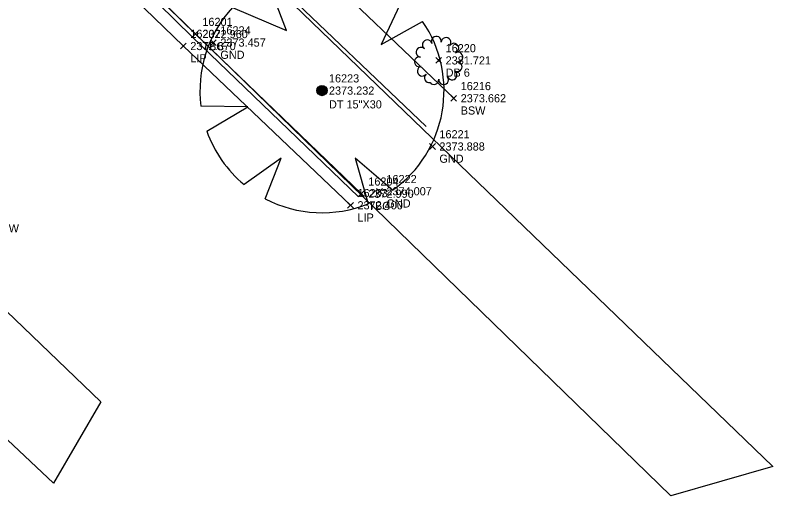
# Model space of a CAD drawing. Extents: x 2377639 to 2379738, y 729875 to 732734.
# Drawn here: x 2378181.6 to 2378274.7, y 730250.4 to 730309.5 of the extents above; entities that cross this region are included whole.
import ezdxf

# ---------------------------------------------------------------- set-up
doc = ezdxf.new("R2010")
doc.units = 0
for name, color, linetype in [('Default', 7, 'Continuous'), ('TOPO_CURBGTR_Back-of-Curb', 7, 'Continuous'), ('TOPO_CURBGTR_Face-of-Curb', 7, 'Continuous'), ('TOPO_CURBGTR_Lip-of-Gutter', 7, 'Continuous'), ('TOPO_DATA_Elevations', 7, 'Continuous'), ('TOPO_LNDSCP_Misc', 7, 'Continuous'), ('TOPO_LNDSCP_Tree', 7, 'Continuous'), ('TOPO_SW_Back', 7, 'Continuous')]:
    doc.layers.add(name, color=color, linetype=linetype)

# ---------------------------------------------------------------- blocks, each defined once
blk = doc.blocks.new('DB_2')
at = {"layer": 'Default'}
for centre, radius, start, end in [((-0.0121, 0.0998), 0.0254, 347.9823, 206.2388), ((0.0381, 0.0934), 0.0254, 319.1823, 177.4388), ((-0.0592, 0.0812), 0.0254, 16.7823, 235.0388), ((0.079, 0.0636), 0.0254, 290.3823, 148.6388), ((-0.0916, 0.0423), 0.0254, 45.5823, 263.8388), ((0.1005, 0.0177), 0.0254, 261.5823, 119.8388), ((-0.1011, -0.0074), 0.0254, 74.3823, 292.6388), ((0, 0), 0.00318, 0, 180), ((0, 0), 0.00318, 180, 0), ((-0.0856, -0.0556), 0.0254, 103.1823, 321.4388), ((0.0972, -0.0328), 0.0254, 232.7823, 91.0388), ((-0.0487, -0.0903), 0.0254, 131.9823, 278.4601), ((0.07, -0.0755), 0.0254, 203.9823, 62.2388), ((-0.025, -0.0997), 0.0254, 218.161, 4.6388), ((0.0256, -0.0998), 0.0254, 175.1823, 33.4388)]:
    blk.add_arc(centre, radius, start, end, dxfattribs=at)
blk = doc.blocks.new('DT_2')
at = {"layer": 'Default'}
for p, q in [((-0.03698, 0.06247), (-0.05646, 0.11375)), ((0.08381, 0.0954), (0.06151, 0.04792)), ((-0.09298, 0.0865), (-0.03698, 0.06247)), ((0.06151, 0.04792), (0.10461, 0.072)), ((-0.07727, -0.017), (-0.12593, -0.01636)), ((-0.11978, -0.04218), (-0.07727, -0.017)), ((-0.04258, -0.07017), (-0.0811, -0.09772)), ((-0.05897, -0.11247), (-0.04258, -0.07017)), ((0.07336, -0.10366), (0.03465, -0.07017)), ((0.03465, -0.07017), (0.04801, -0.11757))]:
    blk.add_line(p, q, dxfattribs=at)
for start, end in [(48.70125, 116.39792), (137.06823, 187.40379), (305.28646, 34.53794), (199.39852, 230.30841), (242.32871, 292.21141)]:
    blk.add_arc((0, 0), 0.12699, start, end, dxfattribs=at)
blk = doc.blocks.new('STUMP_4')
at = {"layer": 'Default'}
for q in [(-0.0106, 0.0008), (-0.0106, 0), (-0.0106, -0.0008), (-0.0105, 0.0017), (-0.0105, -0.0017), (-0.0103, 0.0025), (-0.0103, -0.0025), (-0.0101, 0.0033), (-0.0101, -0.0033), (-0.0098, 0.004), (-0.0098, -0.004), (-0.0094, 0.0048), (-0.0094, -0.0048), (-0.009, 0.0055), (-0.009, -0.0055), (-0.0086, 0.0062), (-0.0086, -0.0062), (-0.008, 0.0069), (-0.008, -0.0069), (-0.0075, 0.0075), (-0.0075, -0.0075), (-0.0069, 0.008), (-0.0069, -0.008), (-0.0062, 0.0086), (-0.0062, -0.0086), (-0.0055, 0.009), (-0.0055, -0.009), (-0.0048, 0.0094), (-0.0048, -0.0094), (-0.004, 0.0098), (-0.004, -0.0098), (-0.0033, 0.0101), (-0.0033, -0.0101), (-0.0025, 0.0103), (-0.0025, -0.0103), (-0.0017, 0.0105), (-0.0017, -0.0105), (-0.0008, 0.0106), (-0.0008, -0.0106), (0, 0.0106), (0.0008, 0.0106), (0.0017, 0.0105), (0.0025, 0.0103), (0.0033, 0.0101), (0.004, 0.0098), (0.0048, 0.0094), (0.0055, 0.009), (0.0062, 0.0086), (0.0069, 0.008), (0.0075, 0.0075), (0.008, 0.0069), (0.0086, 0.0062), (0.009, 0.0055), (0.0094, 0.0048), (0.0098, 0.004), (0.0101, 0.0033), (0.0103, 0.0025), (0.0105, 0.0017), (0.0106, 0.0008), (0.0062, -0.0086), (0.0069, -0.008), (0.0075, -0.0075), (0.008, -0.0069), (0.0086, -0.0062), (0.009, -0.0055), (0.004, -0.0098), (0.0048, -0.0094), (0.0055, -0.009), (0.0094, -0.0048), (0.0098, -0.004), (0.0101, -0.0033), (0.0103, -0.0025), (0.0105, -0.0017), (0.0106, -0.0008), (0.0106, 0), (0, -0.0106), (0.0008, -0.0106), (0.0017, -0.0105), (0.0025, -0.0103), (0.0033, -0.0101)]:
    blk.add_line((0, 0), q, dxfattribs=at)
blk.add_circle((0, 0), 0.0106, dxfattribs=at)

msp = doc.modelspace()

# ---------------------------------------------------------------- linework, layer by layer
at = {"layer": 'TOPO_CURBGTR_Back-of-Curb'}
msp.add_lwpolyline([(2378195.23, 730315.426), (2378203.719, 730307.132), (2378224.111, 730287.528)], dxfattribs=at)
at = {"layer": 'TOPO_CURBGTR_Face-of-Curb'}
msp.add_lwpolyline([(2378194.906, 730315.045), (2378203.371, 730306.773), (2378223.764, 730287.168)], dxfattribs=at)
at = {"layer": 'TOPO_CURBGTR_Lip-of-Gutter'}
msp.add_lwpolyline([(2378193.91, 730313.764), (2378202.238, 730305.665), (2378222.78, 730286.111)], dxfattribs=at)
at = {"layer": 'TOPO_DATA_Elevations'}
for p, q in [((2378203.365, 730306.778), (2378204.073, 730307.486)), ((2378203.365, 730307.486), (2378204.073, 730306.778)), ((2378203.365, 730306.778), (2378204.073, 730307.486)), ((2378203.365, 730307.486), (2378204.073, 730306.778)), ((2378201.884, 730305.311), (2378202.592, 730306.019)), ((2378201.884, 730306.019), (2378202.592, 730305.311)), ((2378201.884, 730305.311), (2378202.592, 730306.019)), ((2378201.884, 730306.019), (2378202.592, 730305.311)), ((2378205.575, 730305.738), (2378206.283, 730306.446)), ((2378205.575, 730306.446), (2378206.283, 730305.738)), ((2378205.575, 730305.738), (2378206.283, 730306.446)), ((2378205.575, 730306.446), (2378206.283, 730305.738)), ((2378233.258, 730303.544), (2378233.966, 730304.252)), ((2378233.258, 730304.252), (2378233.966, 730303.544)), ((2378233.258, 730303.544), (2378233.966, 730304.252)), ((2378233.258, 730304.252), (2378233.966, 730303.544)), ((2378218.92, 730299.84), (2378219.628, 730300.548)), ((2378218.92, 730300.548), (2378219.628, 730299.84)), ((2378218.92, 730299.84), (2378219.628, 730300.548)), ((2378218.92, 730300.548), (2378219.628, 730299.84)), ((2378235.109, 730298.895), (2378235.817, 730299.603)), ((2378235.109, 730299.603), (2378235.817, 730298.895)), ((2378235.109, 730298.895), (2378235.817, 730299.603)), ((2378235.109, 730299.603), (2378235.817, 730298.895)), ((2378232.497, 730292.977), (2378233.205, 730293.685)), ((2378232.497, 730293.685), (2378233.205, 730292.977)), ((2378232.497, 730292.977), (2378233.205, 730293.685)), ((2378232.497, 730293.685), (2378233.205, 730292.977)), ((2378223.757, 730287.174), (2378224.465, 730287.882)), ((2378223.757, 730287.882), (2378224.465, 730287.174)), ((2378223.757, 730287.174), (2378224.465, 730287.882)), ((2378223.757, 730287.882), (2378224.465, 730287.174)), ((2378225.984, 730287.48), (2378226.692, 730288.188)), ((2378225.984, 730288.188), (2378226.692, 730287.48)), ((2378225.984, 730287.48), (2378226.692, 730288.188)), ((2378225.984, 730288.188), (2378226.692, 730287.48)), ((2378222.426, 730285.757), (2378223.134, 730286.465)), ((2378222.426, 730286.465), (2378223.134, 730285.757)), ((2378222.426, 730285.757), (2378223.134, 730286.465)), ((2378222.426, 730286.465), (2378223.134, 730285.757))]:
    msp.add_line(p, q, dxfattribs=at)
at = {"layer": 'TOPO_LNDSCP_Misc'}
msp.add_lwpolyline([(2378190.949, 730319.069), (2378198.832, 730327.158), (2378274.679, 730254.052), (2378262.15, 730250.433), (2378195.23, 730315.426), (2378191.039, 730318.986)], dxfattribs=at)
msp.add_lwpolyline([(2378158.703, 730277.883), (2378166.731, 730286.27), (2378192.104, 730261.983), (2378186.28, 730251.999)], close=True, dxfattribs=at)
at = {"layer": 'TOPO_SW_Back'}
for points in [[(2378208.296, 730325.361), (2378216.997, 730316.91), (2378235.463, 730299.249)], [(2378204.914, 730321.877), (2378213.615, 730313.426), (2378232.081, 730295.765)]]:
    msp.add_lwpolyline(points, dxfattribs=at)

# ---------------------------------------------------------------- block references
at = {"layer": 'TOPO_LNDSCP_Tree'}
for name, p, xscale, yscale in [('DT_2', (2378219.274, 730300.194), 118.11000000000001, 118.11000000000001), ('DB_2', (2378233.612, 730303.898), 23.622, 23.622), ('STUMP_4', (2378219.274, 730300.194), 59.05500000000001, 59.05500000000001)]:
    msp.add_blockref(name, p, dxfattribs=dict(at, xscale=xscale, yscale=yscale))

# ---------------------------------------------------------------- texts
at = {"layer": 'TOPO_DATA_Elevations'}
for s, p in [('16201', (2378204.573, 730308.132)), ('16201', (2378204.573, 730308.132)), ('16202', (2378203.092, 730306.665)), ('16202', (2378203.092, 730306.665)), ('2372.960', (2378204.573, 730306.632)), ('2372.960', (2378204.573, 730306.632)), ('16224', (2378206.783, 730307.092)), ('16224', (2378206.783, 730307.092)), ('2373.457', (2378206.783, 730305.592)), ('2373.457', (2378206.783, 730305.592)), ('2372.670', (2378203.092, 730305.165)), ('2372.670', (2378203.092, 730305.165)), ('TBC', (2378204.573, 730305.132)), ('TBC', (2378204.573, 730305.132)), ('16220', (2378234.466, 730304.898)), ('16220', (2378234.466, 730304.898)), ('LIP', (2378203.092, 730303.665)), ('LIP', (2378203.092, 730303.665)), ('GND', (2378206.783, 730304.092)), ('GND', (2378206.783, 730304.092)), ('2381.721', (2378234.466, 730303.398)), ('2381.721', (2378234.466, 730303.398)), ('DB 6', (2378234.466, 730301.898)), ('DB 6', (2378234.466, 730301.898)), ('16223', (2378220.128, 730301.194)), ('16223', (2378220.128, 730301.194)), ('16216', (2378236.317, 730300.249)), ('16216', (2378236.317, 730300.249)), ('2373.232', (2378220.128, 730299.694)), ('2373.232', (2378220.128, 730299.694)), ('DT 15"X30', (2378220.128, 730298.004)), ('DT 15"X30', (2378220.128, 730298.004)), ('2373.662', (2378236.317, 730298.749)), ('2373.662', (2378236.317, 730298.749)), ('BSW', (2378236.317, 730297.249)), ('BSW', (2378236.317, 730297.249)), ('16221', (2378233.705, 730294.331)), ('16221', (2378233.705, 730294.331)), ('2373.888', (2378233.705, 730292.831)), ('2373.888', (2378233.705, 730292.831)), ('GND', (2378233.705, 730291.331)), ('GND', (2378233.705, 730291.331)), ('16222', (2378227.192, 730288.834)), ('16222', (2378227.192, 730288.834)), ('16204', (2378224.965, 730288.528)), ('16204', (2378224.965, 730288.528)), ('16203', (2378223.634, 730287.111)), ('16203', (2378223.634, 730287.111)), ('2372.990', (2378224.965, 730287.028)), ('2372.990', (2378224.965, 730287.028)), ('2374.007', (2378227.192, 730287.334)), ('2374.007', (2378227.192, 730287.334)), ('2372.400', (2378223.634, 730285.611)), ('2372.400', (2378223.634, 730285.611)), ('TBC', (2378224.965, 730285.528)), ('TBC', (2378224.965, 730285.528)), ('GND', (2378227.192, 730285.834)), ('GND', (2378227.192, 730285.834)), ('LIP', (2378223.634, 730284.111)), ('LIP', (2378223.634, 730284.111)), ('-2.95INV 8"RCP W', (2378170.712, 730282.788)), ('-2.95INV 8"RCP W', (2378170.712, 730282.788))]:
    msp.add_text(s, height=1, dxfattribs=at).set_placement(p)

doc.saveas('drawing.dxf')
